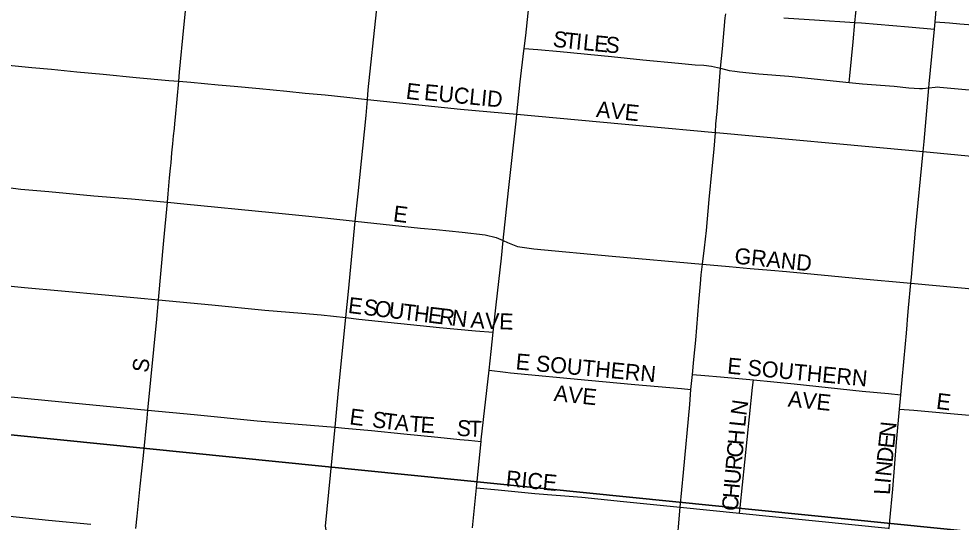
# Model space of a CAD drawing. Extents: x -209 to 4852, y 0 to 905.
# Drawn here: x 111.69 to 122.82, y 254.19 to 260.14 of the extents above; entities that cross this region are included whole.
import ezdxf

# ---------------------------------------------------------------- set-up
doc = ezdxf.new("R2010")
doc.units = 0
for name, color, linetype in [('GM_X_Airport_Location_Class_2', 7, 'Continuous'), ('GM_X_Airport_Location_Class_3', 7, 'Continuous'), ('GM_X_County_Subdivision_Text', 7, 'Continuous'), ('GM_X_Minor_River', 7, 'Continuous')]:
    doc.layers.add(name, color=color, linetype=linetype)

msp = doc.modelspace()

# ---------------------------------------------------------------- linework, layer by layer
at = {"layer": 'GM_X_Airport_Location_Class_2'}
for points in [[(121.57, 260.099), (121.581, 260.207), (121.642, 260.827), (121.706, 261.506), (121.751, 262), (121.851, 263.004), (121.903, 263.545), (121.92, 263.705), (121.932, 263.816)], [(122.519, 260.105), (122.519, 260.11), (122.587, 260.912), (122.66, 261.651), (122.735, 262.46), (122.784, 263.009), (122.792, 263.07), (122.818, 263.271)], [(113.579, 259.404), (113.589, 259.512), (113.639, 260.038), (113.681, 260.473), (113.708, 260.771)], [(115.81, 259.186), (115.818, 259.302), (115.916, 260.225), (115.94, 260.472), (115.948, 260.562)], [(119.981, 259.559), (120.003, 259.787), (120.038, 260.154), (120.043, 260.199)], [(120.731, 260.154), (120.784, 260.15), (121.091, 260.131), (121.57, 260.099)], [(121.501, 259.388), (121.509, 259.469), (121.547, 259.87), (121.57, 260.099)], [(121.57, 260.099), (121.647, 260.094), (122.204, 260.046), (122.51, 260.02)], [(122.442, 259.326), (122.447, 259.371), (122.51, 260.02)], [(122.51, 260.02), (122.519, 260.105)], [(122.519, 260.105), (122.686, 260.092), (122.809, 260.083), (123.741, 260.009), (124.114, 259.984), (125.298, 259.881), (125.982, 259.821), (126.367, 259.791), (126.509, 259.779)], [(117.661, 259.79), (117.823, 259.777), (118.088, 259.755), (118.691, 259.694), (119.063, 259.656), (119.483, 259.617), (119.681, 259.598), (119.784, 259.592), (119.876, 259.581), (119.981, 259.559)], [(111.394, 259.608), (111.527, 259.597), (111.844, 259.567), (112.075, 259.545), (112.373, 259.516), (112.687, 259.486), (113.077, 259.449), (113.461, 259.413), (113.579, 259.404)], [(119.92, 258.796), (119.927, 258.898), (119.942, 259.045), (119.981, 259.559)], [(119.981, 259.559), (120.083, 259.531), (120.149, 259.522), (120.206, 259.515), (120.432, 259.492), (120.788, 259.462), (121.501, 259.388)], [(113.445, 257.972), (113.454, 258.072), (113.471, 258.262), (113.482, 258.374), (113.488, 258.437), (113.499, 258.556), (113.509, 258.664), (113.518, 258.756), (113.527, 258.846), (113.532, 258.904), (113.539, 258.978), (113.579, 259.404)], [(113.579, 259.404), (113.723, 259.393), (114.043, 259.362), (114.232, 259.344), (114.535, 259.316), (114.858, 259.285), (115.074, 259.264), (115.311, 259.242), (115.566, 259.216), (115.81, 259.186)], [(121.501, 259.388), (121.658, 259.372), (122.035, 259.343), (122.207, 259.327), (122.331, 259.318), (122.369, 259.318), (122.442, 259.326)], [(122.377, 258.573), (122.388, 258.692), (122.442, 259.326)], [(122.442, 259.326), (122.517, 259.334), (122.547, 259.336), (122.574, 259.335), (123.529, 259.248), (123.696, 259.231), (123.978, 259.224), (124.191, 259.204), (124.488, 259.175), (124.808, 259.144), (125.083, 259.129), (125.385, 259.105), (125.576, 259.084), (126.185, 259.029), (126.316, 259.014), (126.438, 258.999)], [(115.665, 257.749), (115.7, 258.073), (115.793, 258.997), (115.81, 259.186)], [(115.81, 259.186), (116.907, 259.074), (117.575, 259.013)], [(117.575, 259.013), (119.067, 258.877), (119.92, 258.796)], [(119.769, 257.24), (119.792, 257.434), (119.814, 257.64), (119.847, 258.006), (119.883, 258.368), (119.906, 258.6), (119.92, 258.796)], [(119.92, 258.796), (119.928, 258.796), (122.25, 258.585), (122.377, 258.573)], [(122.232, 257.016), (122.239, 257.088), (122.284, 257.644), (122.377, 258.573)], [(122.377, 258.573), (122.989, 258.515), (124.47, 258.395), (126.366, 258.231)], [(111.263, 258.205), (111.363, 258.179), (111.415, 258.167), (111.455, 258.16), (111.563, 258.146), (111.711, 258.128), (112.043, 258.1), (112.577, 258.05), (113.02, 258.014), (113.445, 257.972)], [(113.339, 256.818), (113.403, 257.521), (113.445, 257.972)], [(113.445, 257.972), (113.639, 257.953), (114.683, 257.85), (115.116, 257.809), (115.342, 257.785), (115.665, 257.749)], [(115.552, 256.608), (115.585, 256.919), (115.665, 257.749)], [(115.665, 257.749), (116.437, 257.666), (116.62, 257.65), (116.928, 257.617), (117.201, 257.589), (117.33, 257.557), (117.413, 257.52)], [(117.413, 257.52), (117.465, 257.496), (117.581, 257.451), (117.774, 257.42), (118.699, 257.336), (119.769, 257.24)], [(119.649, 255.937), (119.665, 256.113), (119.689, 256.34), (119.725, 256.79), (119.746, 257.006), (119.753, 257.115), (119.769, 257.24)], [(119.769, 257.24), (120.084, 257.212), (120.33, 257.189), (120.575, 257.168), (120.759, 257.152), (121.62, 257.07), (122.232, 257.016)], [(111.149, 257.022), (111.486, 256.991), (111.756, 256.966), (112.193, 256.926), (112.709, 256.879), (113.176, 256.834), (113.339, 256.818)], [(122.113, 255.695), (122.129, 255.871), (122.168, 256.3), (122.179, 256.426), (122.187, 256.525), (122.192, 256.587), (122.204, 256.724), (122.232, 257.016)], [(122.232, 257.016), (123.041, 256.941), (123.536, 256.902), (125.389, 256.744), (125.821, 256.704), (126.218, 256.668)], [(113.214, 255.516), (113.319, 256.591), (113.339, 256.818)], [(113.339, 256.818), (113.968, 256.758), (114.595, 256.698), (115.033, 256.661), (115.261, 256.641), (115.552, 256.608)], [(115.426, 255.314), (115.468, 255.746), (115.552, 256.608)], [(115.552, 256.608), (115.708, 256.591), (116.66, 256.491), (117.086, 256.454), (117.295, 256.435)], [(117.246, 255.988), (117.44, 255.963), (117.501, 255.955), (118.418, 255.869), (118.968, 255.819), (119.519, 255.769), (119.632, 255.759)], [(119.632, 255.759), (119.649, 255.937)], [(119.649, 255.937), (119.795, 255.925), (119.981, 255.909), (120.369, 255.871)], [(120.207, 254.295), (120.215, 254.362), (120.324, 255.434), (120.36, 255.784), (120.369, 255.871)], [(120.369, 255.871), (120.85, 255.824), (121.655, 255.74), (121.965, 255.71), (122.113, 255.695)], [(111.03, 255.729), (111.478, 255.685), (112.034, 255.629), (113.214, 255.516)], [(119.506, 254.367), (119.544, 254.778), (119.617, 255.583), (119.632, 255.759)], [(122.098, 255.528), (122.113, 255.695)], [(113.072, 254.114), (113.087, 254.26), (113.125, 254.614), (113.163, 254.98), (113.205, 255.421), (113.214, 255.516)], [(113.214, 255.516), (113.76, 255.463), (114.505, 255.389), (115.426, 255.314)], [(121.974, 254.117), (121.983, 254.211), (122.017, 254.58), (122.062, 255.136), (122.098, 255.528)], [(122.098, 255.528), (122.267, 255.513), (124.484, 255.314), (124.791, 255.29), (125.343, 255.242), (125.526, 255.224), (126.079, 255.176)], [(115.42, 253.887), (115.334, 254.063), (115.32, 254.101), (115.313, 254.142), (115.39, 254.946), (115.426, 255.314)], [(115.426, 255.314), (115.542, 255.303), (115.857, 255.272), (116.239, 255.234), (116.641, 255.195), (116.899, 255.169), (117.003, 255.159), (117.151, 255.144)], [(117.098, 254.596), (117.354, 254.572), (117.786, 254.531), (118.341, 254.485), (118.833, 254.435), (119.506, 254.367)], [(119.375, 252.947), (119.377, 252.972), (119.421, 253.451), (119.431, 253.565), (119.459, 253.856), (119.506, 254.367)], [(119.506, 254.367), (120.207, 254.295)], [(110.895, 254.329), (111.024, 254.316), (111.236, 254.295), (112.038, 254.215), (112.54, 254.165)], [(120.207, 254.295), (121.961, 254.118), (121.974, 254.117)]]:
    msp.add_lwpolyline(points, dxfattribs=at)
at = {"layer": 'GM_X_County_Subdivision_Text'}
msp.add_lwpolyline([(117.05, 254.122), (117.098, 254.596), (117.151, 255.144), (117.153, 255.165), (117.246, 255.988), (117.271, 256.208), (117.295, 256.435), (117.328, 256.759), (117.391, 257.312), (117.413, 257.52), (117.476, 258.113), (117.57, 258.968), (117.575, 259.013), (117.615, 259.397), (117.658, 259.763), (117.661, 259.79), (117.679, 259.944), (117.729, 260.4), (117.753, 260.62), (117.835, 261.36), (117.979, 262.719), (118.028, 263.213), (118.057, 263.518), (118.068, 263.692)], dxfattribs=at)
at = {"layer": 'GM_X_Minor_River'}
for points in [[(108.909, 275.428), (129.104, 273.545), (127.195, 253.652), (106.979, 255.688)], [(106.979, 255.688), (127.195, 253.652), (125.307, 233.161), (105.036, 235.054)]]:
    msp.add_lwpolyline(points, close=True, dxfattribs=at)

# ---------------------------------------------------------------- texts
at = {"layer": 'GM_X_Airport_Location_Class_3'}
for s, height, rotation, p in [('S', 0.189, 351.9703, (117.992, 259.815)), ('T', 0.189, 354.0846, (118.132, 259.795)), ('I', 0.189, 354.4482, (118.266, 259.781)), ('L', 0.189, 354.4172, (118.349, 259.773)), ('E', 0.189, 354.4333, (118.481, 259.76)), ('S', 0.189, 354.4283, (118.614, 259.747)), ('E', 0.189, 352.8817, (116.256, 259.198)), ('EUCLID', 0.1894, 354.3997, (116.472, 259.182)), ('AVE', 0.1894, 354.0969, (118.506, 258.982)), ('E', 0.189, 352.8783, (116.106, 257.748)), ('GRAND', 0.1894, 354.1729, (120.14, 257.248)), ('E', 0.189, 353.1258, (115.573, 256.665)), ('S', 0.189, 353.1122, (115.755, 256.643)), ('O', 0.189, 353.1357, (115.887, 256.627)), ('U', 0.189, 353.1216, (116.053, 256.607)), ('T', 0.189, 353.1274, (116.218, 256.587)), ('H', 0.189, 353.1184, (116.351, 256.571)), ('E', 0.189, 353.1274, (116.516, 256.551)), ('R', 0.189, 353.1226, (116.648, 256.535)), ('N', 0.189, 353.1306, (116.797, 256.517)), ('A', 0.189, 355.9165, (117.022, 256.49)), ('V', 0.189, 357.893, (117.196, 256.478)), ('E', 0.189, 357.9581, (117.363, 256.472)), ('S', 0.189, 82.8783, (113.216, 255.951)), ('E SOUTHERN', 0.1894, 354.6857, (117.555, 255.998)), ('E SOUTHERN', 0.1894, 354.686, (120.055, 255.948)), ('AVE', 0.1894, 354.0932, (118.005, 255.624)), ('AVE', 0.1894, 354.0932, (120.772, 255.558)), ('E', 0.189, 352.8783, (122.523, 255.532)), ('N', 0.189, 81.7972, (120.286, 255.442)), ('E', 0.189, 352.8649, (115.59, 255.348)), ('S', 0.189, 352.6175, (115.856, 255.315)), ('T', 0.189, 352.6175, (115.989, 255.298)), ('A', 0.189, 353.8299, (116.125, 255.28)), ('T', 0.189, 355.9756, (116.299, 255.262)), ('L', 0.189, 84.061, (120.272, 255.311)), ('E', 0.189, 356.1968, (116.432, 255.252)), ('S', 0.189, 354.7054, (116.857, 255.215)), ('T', 0.189, 358.7128, (117.004, 255.202)), ('N', 0.189, 84.1752, (122.045, 255.188)), ('H', 0.189, 84.857, (120.253, 255.096)), ('E', 0.189, 84.1711, (122.031, 255.056)), ('C', 0.189, 84.8639, (120.24, 254.947)), ('D', 0.189, 84.1763, (122.014, 254.89)), ('R', 0.189, 84.8693, (120.226, 254.798)), ('N', 0.189, 84.2415, (121.998, 254.724)), ('RICE', 0.1894, 354.6433, (117.439, 254.615)), ('U', 0.189, 84.8739, (120.211, 254.632)), ('I', 0.189, 84.6156, (121.99, 254.641)), ('H', 0.189, 84.857, (120.196, 254.465)), ('L', 0.189, 86.9111, (121.983, 254.51)), ('C', 0.189, 84.8693, (120.183, 254.316))]:
    msp.add_text(s, height=height, rotation=rotation, dxfattribs=at).set_placement(p)

doc.saveas('drawing.dxf')
